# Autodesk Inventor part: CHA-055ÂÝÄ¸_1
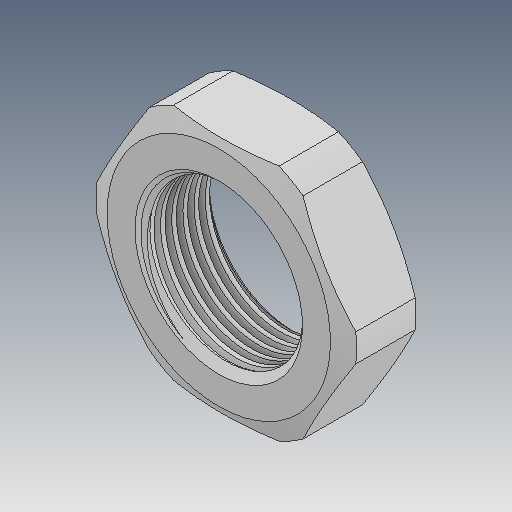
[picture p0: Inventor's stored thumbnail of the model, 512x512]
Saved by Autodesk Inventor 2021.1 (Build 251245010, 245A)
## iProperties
Created: 2019-12
Part Number: CHA-055ÂÝÄ¸_1
Material: Ogólny
Document SubType Name: Modeling
Designer: user
Density: 1 g/cm^3
Appearance: Domyślna
Author: user
Revision Number: ÈÎºÎ
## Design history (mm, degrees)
feature "ÊäÈë1"
node "Bryła1"
